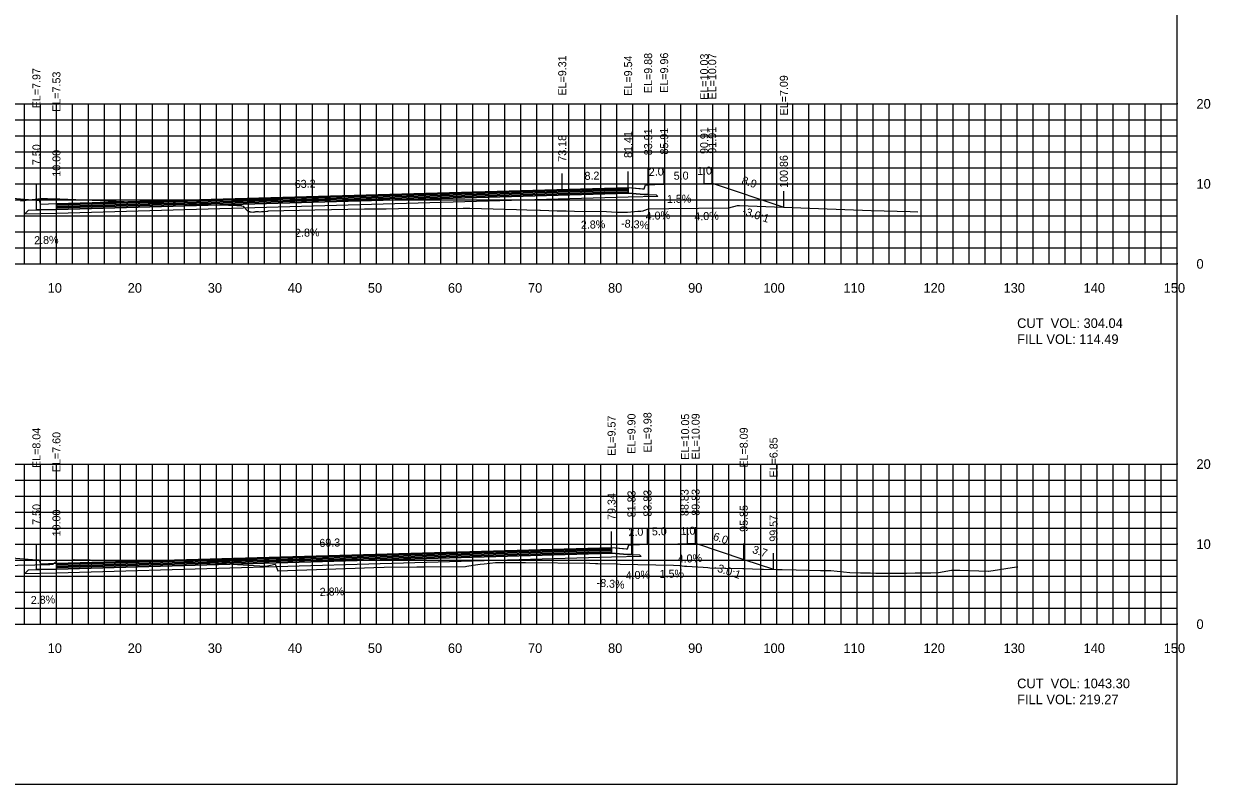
# Model space of a CAD drawing. Extents: x 1797419 to 1809236, y 248759 to 251512.
# Drawn here: x 1806376.9 to 1806525.1, y 250079.4 to 250174.4 of the extents above; entities that cross this region are included whole.
import ezdxf

# ---------------------------------------------------------------- set-up
doc = ezdxf.new("R2010")
doc.units = 0
for name, color, linetype in [('10', 7, 'Continuous'), ('3', 7, 'Continuous'), ('31', 7, 'Continuous'), ('4', 7, 'Continuous'), ('60', 7, 'Continuous'), ('ANNO-TXT', 7, 'Continuous'), ('BASE', 7, 'Continuous'), ('CL-CNST', 7, 'Continuous'), ('Level 62', 7, 'Continuous'), ('LOWER BINDER', 7, 'Continuous'), ('M-ROADS', 7, 'Continuous'), ('UPPER BINDER', 7, 'Continuous'), ('WEARING', 7, 'Continuous')]:
    doc.layers.add(name, color=color, linetype=linetype)

msp = doc.modelspace()

# ---------------------------------------------------------------- linework, layer by layer
for p, q in [((1806461.91, 250154.46), (1806461.91, 250156.46)), ((1806462.91, 250154.5), (1806462.91, 250156.5)), ((1806444.18, 250153.74), (1806444.18, 250155.74)), ((1806452.41, 250153.97), (1806452.41, 250155.97)), ((1806454.91, 250154.31), (1806454.91, 250156.31)), ((1806456.91, 250154.39), (1806456.91, 250156.39)), ((1806378.5, 250152.41), (1806378.5, 250154.41)), ((1806381, 250151.96), (1806381, 250153.96)), ((1806381, 250151.96), (1806381, 250153.96)), ((1806471.86, 250151.52), (1806471.86, 250153.52)), ((1806450.34, 250109), (1806450.34, 250111)), ((1806452.83, 250109.33), (1806452.83, 250111.33)), ((1806454.83, 250109.41), (1806454.83, 250111.41)), ((1806459.83, 250109.49), (1806459.83, 250111.49)), ((1806460.84, 250109.53), (1806460.84, 250111.53)), ((1806378.5, 250107.48), (1806378.5, 250109.48)), ((1806381, 250107.03), (1806381, 250109.03)), ((1806381, 250107.03), (1806381, 250109.03)), ((1806466.85, 250107.52), (1806466.85, 250109.52)), ((1806470.57, 250106.28), (1806470.57, 250108.28))]:
    msp.add_line(p, q)
for points in [[(1806221, 250079.43), (1806521, 250079.43), (1806521, 250269.43), (1806221, 250269.43)], [(1806452.41, 250153.97), (1806454.41, 250153.81), (1806454.58, 250154.31), (1806454.91, 250154.31), (1806454.91, 250153.09), (1806454.41, 250153.09), (1806452.41, 250153.25)], [(1806378.5, 250152.41), (1806378.83, 250152.41), (1806379, 250151.91), (1806381, 250151.96), (1806381, 250151.24), (1806379, 250151.19), (1806378.5, 250151.19)], [(1806450.34, 250109), (1806452.34, 250108.83), (1806452.5, 250109.33), (1806452.83, 250109.33), (1806452.83, 250108.12), (1806452.34, 250108.12), (1806450.34, 250108.28)], [(1806378.5, 250107.48), (1806378.83, 250107.48), (1806379, 250106.98), (1806381, 250107.03), (1806381, 250106.31), (1806379, 250106.26), (1806378.5, 250106.26)]]:
    msp.add_lwpolyline(points, close=True)
at = {"layer": '60'}
for p, q in [((1806521, 250144.43), (1806521, 250164.43)), ((1806521.06, 250164.43), (1806521, 250164.43)), ((1806521.06, 250154.43), (1806521, 250154.43)), ((1806221, 250144.43), (1806521, 250144.43)), ((1806381, 250144.37), (1806381, 250144.43)), ((1806391, 250144.37), (1806391, 250144.43)), ((1806401, 250144.37), (1806401, 250144.43)), ((1806411, 250144.37), (1806411, 250144.43)), ((1806421, 250144.37), (1806421, 250144.43)), ((1806431, 250144.37), (1806431, 250144.43)), ((1806441, 250144.37), (1806441, 250144.43)), ((1806451, 250144.37), (1806451, 250144.43)), ((1806461, 250144.37), (1806461, 250144.43)), ((1806471, 250144.37), (1806471, 250144.43)), ((1806481, 250144.37), (1806481, 250144.43)), ((1806491, 250144.37), (1806491, 250144.43)), ((1806501, 250144.37), (1806501, 250144.43)), ((1806511, 250144.37), (1806511, 250144.43)), ((1806521, 250144.37), (1806521, 250144.43)), ((1806521.06, 250144.43), (1806521, 250144.43)), ((1806521, 250099.43), (1806521, 250119.43)), ((1806521.06, 250119.43), (1806521, 250119.43)), ((1806521.06, 250109.43), (1806521, 250109.43)), ((1806221, 250099.43), (1806521, 250099.43)), ((1806381, 250099.37), (1806381, 250099.43)), ((1806391, 250099.37), (1806391, 250099.43)), ((1806401, 250099.37), (1806401, 250099.43)), ((1806411, 250099.37), (1806411, 250099.43)), ((1806421, 250099.37), (1806421, 250099.43)), ((1806431, 250099.37), (1806431, 250099.43)), ((1806441, 250099.37), (1806441, 250099.43)), ((1806451, 250099.37), (1806451, 250099.43)), ((1806461, 250099.37), (1806461, 250099.43)), ((1806471, 250099.37), (1806471, 250099.43)), ((1806481, 250099.37), (1806481, 250099.43)), ((1806491, 250099.37), (1806491, 250099.43)), ((1806501, 250099.37), (1806501, 250099.43)), ((1806511, 250099.37), (1806511, 250099.43)), ((1806521, 250099.37), (1806521, 250099.43)), ((1806521.06, 250099.43), (1806521, 250099.43))]:
    msp.add_line(p, q, dxfattribs=at)
at = {"layer": 'BASE'}
for points in [[(1806381, 250151.24), (1806452.41, 250153.25), (1806454.41, 250153.09), (1806454.91, 250153.09), (1806455.91, 250153.07), (1806456.12, 250152.86), (1806452.41, 250152.75), (1806381, 250150.74), (1806377, 250150.63), (1806377.5, 250151.13), (1806378.5, 250151.19), (1806379, 250151.19)], [(1806381, 250106.31), (1806450.34, 250108.28), (1806452.34, 250108.12), (1806452.83, 250108.12), (1806453.83, 250108.1), (1806454.05, 250107.88), (1806450.34, 250107.78), (1806381, 250105.81), (1806377, 250105.7), (1806377.5, 250106.2), (1806378.5, 250106.26), (1806379, 250106.26)]]:
    msp.add_lwpolyline(points, close=True, dxfattribs=at)
at = {"layer": 'CL-CNST'}
for points in [[(1806371, 250153.02), (1806378.5, 250152.41), (1806378.58, 250152.41), (1806378.83, 250152.41), (1806378.98, 250151.96), (1806379, 250151.91), (1806381, 250151.96), (1806381, 250151.96), (1806444.18, 250153.74), (1806452.41, 250153.97), (1806454.21, 250153.82), (1806454.41, 250153.81), (1806454.58, 250154.31), (1806454.78, 250154.31), (1806454.91, 250154.31), (1806455.76, 250154.34), (1806456.91, 250154.39), (1806458.9, 250154.42), (1806461.91, 250154.46), (1806462.91, 250154.5), (1806471.86, 250151.52)], [(1806373.81, 250107.86), (1806378.5, 250107.48), (1806378.83, 250107.48), (1806379, 250106.98), (1806380.17, 250107.01), (1806381, 250107.03), (1806381, 250107.03), (1806450.34, 250109), (1806452.18, 250108.84), (1806452.34, 250108.83), (1806452.34, 250108.85), (1806452.5, 250109.33), (1806452.67, 250109.33), (1806452.83, 250109.33), (1806454.83, 250109.41), (1806458.6, 250109.47), (1806459.83, 250109.49), (1806460.84, 250109.53), (1806466.85, 250107.52), (1806470.57, 250106.28)]]:
    msp.add_lwpolyline(points, dxfattribs=at)
at = {"layer": 'Level 62'}
for p, q in [((1806221, 250164.43), (1806521, 250164.43)), ((1806377, 250144.43), (1806377, 250164.43)), ((1806379, 250144.43), (1806379, 250164.43)), ((1806381, 250144.43), (1806381, 250164.43)), ((1806383, 250144.43), (1806383, 250164.43)), ((1806385, 250144.43), (1806385, 250164.43)), ((1806387, 250144.43), (1806387, 250164.43)), ((1806389, 250144.43), (1806389, 250164.43)), ((1806391, 250144.43), (1806391, 250164.43)), ((1806393, 250144.43), (1806393, 250164.43)), ((1806395, 250144.43), (1806395, 250164.43)), ((1806397, 250144.43), (1806397, 250164.43)), ((1806399, 250144.43), (1806399, 250164.43)), ((1806401, 250144.43), (1806401, 250164.43)), ((1806403, 250144.43), (1806403, 250164.43)), ((1806405, 250144.43), (1806405, 250164.43)), ((1806407, 250144.43), (1806407, 250164.43)), ((1806409, 250144.43), (1806409, 250164.43)), ((1806411, 250144.43), (1806411, 250164.43)), ((1806413, 250144.43), (1806413, 250164.43)), ((1806415, 250144.43), (1806415, 250164.43)), ((1806417, 250144.43), (1806417, 250164.43)), ((1806419, 250144.43), (1806419, 250164.43)), ((1806421, 250144.43), (1806421, 250164.43)), ((1806423, 250144.43), (1806423, 250164.43)), ((1806425, 250144.43), (1806425, 250164.43)), ((1806427, 250144.43), (1806427, 250164.43)), ((1806429, 250144.43), (1806429, 250164.43)), ((1806431, 250144.43), (1806431, 250164.43)), ((1806433, 250144.43), (1806433, 250164.43)), ((1806435, 250144.43), (1806435, 250164.43)), ((1806437, 250144.43), (1806437, 250164.43)), ((1806439, 250144.43), (1806439, 250164.43)), ((1806441, 250144.43), (1806441, 250164.43)), ((1806443, 250144.43), (1806443, 250164.43)), ((1806445, 250144.43), (1806445, 250164.43)), ((1806447, 250144.43), (1806447, 250164.43)), ((1806449, 250144.43), (1806449, 250164.43)), ((1806451, 250144.43), (1806451, 250164.43)), ((1806453, 250144.43), (1806453, 250164.43)), ((1806455, 250144.43), (1806455, 250164.43)), ((1806457, 250144.43), (1806457, 250164.43)), ((1806459, 250144.43), (1806459, 250164.43)), ((1806461, 250144.43), (1806461, 250164.43)), ((1806463, 250144.43), (1806463, 250164.43)), ((1806465, 250144.43), (1806465, 250164.43)), ((1806467, 250144.43), (1806467, 250164.43)), ((1806469, 250144.43), (1806469, 250164.43)), ((1806471, 250144.43), (1806471, 250164.43)), ((1806473, 250144.43), (1806473, 250164.43)), ((1806475, 250144.43), (1806475, 250164.43)), ((1806477, 250144.43), (1806477, 250164.43)), ((1806479, 250144.43), (1806479, 250164.43)), ((1806481, 250144.43), (1806481, 250164.43)), ((1806483, 250144.43), (1806483, 250164.43)), ((1806485, 250144.43), (1806485, 250164.43)), ((1806487, 250144.43), (1806487, 250164.43)), ((1806489, 250144.43), (1806489, 250164.43)), ((1806491, 250144.43), (1806491, 250164.43)), ((1806493, 250144.43), (1806493, 250164.43)), ((1806495, 250144.43), (1806495, 250164.43)), ((1806497, 250144.43), (1806497, 250164.43)), ((1806499, 250144.43), (1806499, 250164.43)), ((1806501, 250144.43), (1806501, 250164.43)), ((1806503, 250144.43), (1806503, 250164.43)), ((1806505, 250144.43), (1806505, 250164.43)), ((1806507, 250144.43), (1806507, 250164.43)), ((1806509, 250144.43), (1806509, 250164.43)), ((1806511, 250144.43), (1806511, 250164.43)), ((1806513, 250144.43), (1806513, 250164.43)), ((1806515, 250144.43), (1806515, 250164.43)), ((1806517, 250144.43), (1806517, 250164.43)), ((1806519, 250144.43), (1806519, 250164.43)), ((1806521, 250144.43), (1806521, 250164.43)), ((1806221, 250162.43), (1806521, 250162.43)), ((1806221, 250160.43), (1806521, 250160.43)), ((1806221, 250158.43), (1806521, 250158.43)), ((1806221, 250156.43), (1806521, 250156.43)), ((1806221, 250154.43), (1806521, 250154.43)), ((1806221, 250152.43), (1806521, 250152.43)), ((1806221, 250150.43), (1806521, 250150.43)), ((1806221, 250148.43), (1806521, 250148.43)), ((1806221, 250146.43), (1806521, 250146.43)), ((1806221, 250144.43), (1806521, 250144.43)), ((1806221, 250119.43), (1806521, 250119.43)), ((1806377, 250099.43), (1806377, 250119.43)), ((1806379, 250099.43), (1806379, 250119.43)), ((1806381, 250099.43), (1806381, 250119.43)), ((1806383, 250099.43), (1806383, 250119.43)), ((1806385, 250099.43), (1806385, 250119.43)), ((1806387, 250099.43), (1806387, 250119.43)), ((1806389, 250099.43), (1806389, 250119.43)), ((1806391, 250099.43), (1806391, 250119.43)), ((1806393, 250099.43), (1806393, 250119.43)), ((1806395, 250099.43), (1806395, 250119.43)), ((1806397, 250099.43), (1806397, 250119.43)), ((1806399, 250099.43), (1806399, 250119.43)), ((1806401, 250099.43), (1806401, 250119.43)), ((1806403, 250099.43), (1806403, 250119.43)), ((1806405, 250099.43), (1806405, 250119.43)), ((1806407, 250099.43), (1806407, 250119.43)), ((1806409, 250099.43), (1806409, 250119.43)), ((1806411, 250099.43), (1806411, 250119.43)), ((1806413, 250099.43), (1806413, 250119.43)), ((1806415, 250099.43), (1806415, 250119.43)), ((1806417, 250099.43), (1806417, 250119.43)), ((1806419, 250099.43), (1806419, 250119.43)), ((1806421, 250099.43), (1806421, 250119.43)), ((1806423, 250099.43), (1806423, 250119.43)), ((1806425, 250099.43), (1806425, 250119.43)), ((1806427, 250099.43), (1806427, 250119.43)), ((1806429, 250099.43), (1806429, 250119.43)), ((1806431, 250099.43), (1806431, 250119.43)), ((1806433, 250099.43), (1806433, 250119.43)), ((1806435, 250099.43), (1806435, 250119.43)), ((1806437, 250099.43), (1806437, 250119.43)), ((1806439, 250099.43), (1806439, 250119.43)), ((1806441, 250099.43), (1806441, 250119.43)), ((1806443, 250099.43), (1806443, 250119.43)), ((1806445, 250099.43), (1806445, 250119.43)), ((1806447, 250099.43), (1806447, 250119.43)), ((1806449, 250099.43), (1806449, 250119.43)), ((1806451, 250099.43), (1806451, 250119.43)), ((1806453, 250099.43), (1806453, 250119.43)), ((1806455, 250099.43), (1806455, 250119.43)), ((1806457, 250099.43), (1806457, 250119.43)), ((1806459, 250099.43), (1806459, 250119.43)), ((1806461, 250099.43), (1806461, 250119.43)), ((1806463, 250099.43), (1806463, 250119.43)), ((1806465, 250099.43), (1806465, 250119.43)), ((1806467, 250099.43), (1806467, 250119.43)), ((1806469, 250099.43), (1806469, 250119.43)), ((1806471, 250099.43), (1806471, 250119.43)), ((1806473, 250099.43), (1806473, 250119.43)), ((1806475, 250099.43), (1806475, 250119.43)), ((1806477, 250099.43), (1806477, 250119.43)), ((1806479, 250099.43), (1806479, 250119.43)), ((1806481, 250099.43), (1806481, 250119.43)), ((1806483, 250099.43), (1806483, 250119.43)), ((1806485, 250099.43), (1806485, 250119.43)), ((1806487, 250099.43), (1806487, 250119.43)), ((1806489, 250099.43), (1806489, 250119.43)), ((1806491, 250099.43), (1806491, 250119.43)), ((1806493, 250099.43), (1806493, 250119.43)), ((1806495, 250099.43), (1806495, 250119.43)), ((1806497, 250099.43), (1806497, 250119.43)), ((1806499, 250099.43), (1806499, 250119.43)), ((1806501, 250099.43), (1806501, 250119.43)), ((1806503, 250099.43), (1806503, 250119.43)), ((1806505, 250099.43), (1806505, 250119.43)), ((1806507, 250099.43), (1806507, 250119.43)), ((1806509, 250099.43), (1806509, 250119.43)), ((1806511, 250099.43), (1806511, 250119.43)), ((1806513, 250099.43), (1806513, 250119.43)), ((1806515, 250099.43), (1806515, 250119.43)), ((1806517, 250099.43), (1806517, 250119.43)), ((1806519, 250099.43), (1806519, 250119.43)), ((1806521, 250099.43), (1806521, 250119.43)), ((1806221, 250117.43), (1806521, 250117.43)), ((1806221, 250115.43), (1806521, 250115.43)), ((1806221, 250113.43), (1806521, 250113.43)), ((1806221, 250111.43), (1806521, 250111.43)), ((1806221, 250109.43), (1806521, 250109.43)), ((1806221, 250107.43), (1806521, 250107.43)), ((1806221, 250105.43), (1806521, 250105.43)), ((1806221, 250103.43), (1806521, 250103.43)), ((1806221, 250101.43), (1806521, 250101.43)), ((1806221, 250099.43), (1806521, 250099.43))]:
    msp.add_line(p, q, dxfattribs=at)
at = {"layer": 'LOWER BINDER'}
for points in [[(1806381, 250151.62), (1806452.41, 250153.63), (1806452.41, 250153.44), (1806381, 250151.44)], [(1806381, 250151.44), (1806452.41, 250153.44), (1806452.41, 250153.25), (1806381, 250151.24)], [(1806381, 250106.69), (1806450.34, 250108.66), (1806450.34, 250108.47), (1806381, 250106.51)], [(1806381, 250106.51), (1806450.34, 250108.47), (1806450.34, 250108.28), (1806381, 250106.31)]]:
    msp.add_lwpolyline(points, close=True, dxfattribs=at)
at = {"layer": 'M-ROADS'}
for points in [[(1806376.5, 250152.32), (1806379.04, 250152.6), (1806379.46, 250152.6), (1806379.86, 250152.6), (1806379.88, 250152.6), (1806381.44, 250152.54), (1806397.48, 250151.9), (1806401.05, 250151.81), (1806401.22, 250151.82), (1806401.46, 250151.81), (1806403.53, 250151.71), (1806403.71, 250151.71), (1806404.01, 250151.71), (1806404.06, 250151.71), (1806404.12, 250151.67), (1806404.38, 250151.63), (1806404.38, 250151.59), (1806404.82, 250151.1), (1806404.85, 250151.1), (1806404.97, 250150.97), (1806404.98, 250150.97), (1806405.01, 250150.97), (1806405.04, 250150.96), (1806405.07, 250150.96), (1806405.1, 250150.96), (1806405.14, 250150.95), (1806405.18, 250150.95), (1806405.22, 250150.95), (1806405.26, 250150.94), (1806405.31, 250150.94), (1806405.67, 250150.91), (1806405.69, 250150.92), (1806405.75, 250150.95), (1806405.75, 250150.95), (1806405.81, 250150.95), (1806405.89, 250150.96), (1806405.98, 250150.96), (1806406.08, 250150.96), (1806406.11, 250150.97), (1806406.22, 250150.96), (1806406.39, 250150.95), (1806406.45, 250150.94), (1806406.62, 250150.96), (1806406.82, 250150.97), (1806406.93, 250150.98), (1806407.27, 250151.02), (1806407.39, 250151.03), (1806407.47, 250151.05), (1806413.26, 250151.18), (1806419.5, 250151.31), (1806422.19, 250151.33), (1806423.71, 250151.34), (1806431.8, 250151.38), (1806431.95, 250151.38), (1806432.63, 250151.38), (1806438.45, 250151.22), (1806439.74, 250151.18), (1806441.39, 250151.15), (1806441.48, 250151.15), (1806443.53, 250151.08), (1806444.69, 250151.06), (1806445.7, 250151.03), (1806449.72, 250150.98), (1806450.34, 250150.94), (1806451.09, 250150.9), (1806451.7, 250150.9), (1806451.85, 250150.9), (1806451.87, 250150.9), (1806452.33, 250150.88), (1806453.63, 250151), (1806453.68, 250151), (1806453.94, 250151.02), (1806453.99, 250151.03), (1806454.28, 250151.07), (1806454.39, 250151.1), (1806454.96, 250151.32), (1806457.49, 250151.37), (1806464.89, 250151.43), (1806464.94, 250151.43), (1806464.95, 250151.43), (1806464.96, 250151.43), (1806465, 250151.45), (1806466.06, 250151.72), (1806466.2, 250151.72), (1806466.25, 250151.72), (1806466.28, 250151.72), (1806466.3, 250151.72), (1806466.31, 250151.72), (1806466.32, 250151.72), (1806466.33, 250151.72), (1806466.33, 250151.72), (1806482.77, 250151.12), (1806487.64, 250150.98), (1806488.58, 250150.94)], [(1806369.63, 250106.68), (1806378.29, 250106.85), (1806379.66, 250106.88), (1806380.14, 250106.88), (1806380.16, 250106.89), (1806380.43, 250106.92), (1806380.43, 250106.92), (1806380.52, 250106.93), (1806380.55, 250106.93), (1806380.56, 250106.93), (1806380.57, 250106.93), (1806380.59, 250106.93), (1806380.59, 250106.93), (1806380.6, 250106.93), (1806381.06, 250107.34), (1806381.15, 250107.43), (1806383.1, 250107.48), (1806383.21, 250107.49), (1806387.25, 250107.41), (1806392.73, 250107.39), (1806397.33, 250107.28), (1806398.1, 250107.22), (1806406.41, 250106.72), (1806407.12, 250106.68), (1806407.16, 250106.68), (1806408.32, 250106.94), (1806408.34, 250106.92), (1806408.37, 250106.84), (1806408.65, 250106.09), (1806418.3, 250106.43), (1806420.66, 250106.51), (1806421.92, 250106.53), (1806426.02, 250106.58), (1806426.93, 250106.59), (1806432.09, 250106.65), (1806432.26, 250106.68), (1806433.06, 250106.79), (1806433.94, 250106.91), (1806434.41, 250106.97), (1806435.85, 250107.15), (1806438.13, 250107.15), (1806439.6, 250107.13), (1806447.62, 250107.03), (1806448.32, 250107.01), (1806448.61, 250107.01), (1806451.1, 250106.95), (1806451.4, 250106.94), (1806458.06, 250106.8), (1806458.88, 250106.74), (1806459.15, 250106.72), (1806459.47, 250106.69), (1806459.76, 250106.67), (1806461.8, 250106.53), (1806462.37, 250106.49), (1806462.61, 250106.48), (1806464.5, 250106.43), (1806464.52, 250106.43), (1806464.58, 250106.43), (1806464.61, 250106.43), (1806466.73, 250106.38), (1806466.83, 250106.37), (1806466.96, 250106.37), (1806468.95, 250106.32), (1806469.32, 250106.31), (1806470.92, 250106.27), (1806470.98, 250106.27), (1806471.25, 250106.27), (1806471.67, 250106.24), (1806473.41, 250106.2), (1806474.99, 250106.17), (1806476.42, 250106.14), (1806477.73, 250106.12), (1806480.09, 250105.9), (1806481.43, 250105.86), (1806482.68, 250105.85), (1806483.37, 250105.81), (1806484.56, 250105.82), (1806486.06, 250105.82), (1806487.19, 250105.82), (1806488.26, 250105.83), (1806489.27, 250105.83), (1806490.23, 250105.84), (1806491.16, 250105.87), (1806492.8, 250106.17), (1806493.84, 250106.16), (1806497.43, 250106.07), (1806497.48, 250106.07), (1806500.9, 250106.6), (1806501.07, 250106.59)]]:
    msp.add_lwpolyline(points, dxfattribs=at)
at = {"layer": 'UPPER BINDER'}
for points in [[(1806381, 250151.81), (1806452.41, 250153.82), (1806452.41, 250153.63), (1806381, 250151.62)], [(1806381, 250106.88), (1806450.34, 250108.85), (1806450.34, 250108.66), (1806381, 250106.69)]]:
    msp.add_lwpolyline(points, close=True, dxfattribs=at)
at = {"layer": 'WEARING'}
for points in [[(1806381, 250151.96), (1806452.41, 250153.97), (1806452.41, 250153.82), (1806381, 250151.81)], [(1806381, 250107.03), (1806450.34, 250109), (1806450.34, 250108.85), (1806381, 250106.88)]]:
    msp.add_lwpolyline(points, close=True, dxfattribs=at)

# ---------------------------------------------------------------- texts
for rotation, p in [(341.5639, (1806466.59, 250150.64)), (341.5676, (1806463.05, 250106.15))]:
    msp.add_text('-3.0:1', height=1, rotation=rotation).set_placement(p)
at = {"layer": '10'}
for s, p in [('10', (1806379.9, 250140.83)), ('20', (1806389.9, 250140.83)), ('30', (1806399.9, 250140.83)), ('40', (1806409.9, 250140.83)), ('50', (1806419.9, 250140.83)), ('60', (1806429.9, 250140.83)), ('70', (1806439.9, 250140.83)), ('80', (1806449.9, 250140.83)), ('90', (1806459.9, 250140.83)), ('100', (1806469.3, 250140.83)), ('110', (1806479.3, 250140.83)), ('120', (1806489.3, 250140.83)), ('130', (1806499.3, 250140.83)), ('140', (1806509.3, 250140.83)), ('150', (1806519.3, 250140.83)), ('10', (1806379.9, 250095.83)), ('20', (1806389.9, 250095.83)), ('30', (1806399.9, 250095.83)), ('40', (1806409.9, 250095.83)), ('50', (1806419.9, 250095.83)), ('60', (1806429.9, 250095.83)), ('70', (1806439.9, 250095.83)), ('80', (1806449.9, 250095.83)), ('90', (1806459.9, 250095.83)), ('100', (1806469.3, 250095.83)), ('110', (1806479.3, 250095.83)), ('120', (1806489.3, 250095.83)), ('130', (1806499.3, 250095.83)), ('140', (1806509.3, 250095.83)), ('150', (1806519.3, 250095.83))]:
    msp.add_text(s, height=1.2, dxfattribs=at).set_placement(p)
at = {"layer": '3'}
for s, p in [('EL=9.31', (1806444.68, 250165.46)), ('EL=9.54', (1806452.91, 250165.44)), ('EL=9.88', (1806455.41, 250165.77)), ('EL=9.96', (1806457.41, 250165.8)), ('EL=10.03', (1806462.41, 250164.93)), ('EL=10.07', (1806463.41, 250164.97)), ('EL=7.97', (1806379, 250163.87)), ('EL=7.53', (1806381.5, 250163.43)), ('EL=7.53', (1806381.5, 250163.43)), ('EL=7.09', (1806472.36, 250162.98)), ('81.41', (1806452.91, 250157.67)), ('83.91', (1806455.41, 250158.01)), ('85.91', (1806457.41, 250158.09)), ('90.91', (1806462.41, 250158.16)), ('91.91', (1806463.41, 250158.2)), ('73.18', (1806444.68, 250157.19)), ('7.50', (1806379, 250156.77)), ('10.00', (1806381.5, 250155.33)), ('10.00', (1806381.5, 250155.33)), ('100.86', (1806472.36, 250153.93)), ('EL=9.57', (1806450.84, 250120.46)), ('EL=9.90', (1806453.33, 250120.72)), ('EL=9.98', (1806455.33, 250120.88)), ('EL=10.05', (1806460.03, 250119.96)), ('EL=10.09', (1806461.34, 250120)), ('EL=8.04', (1806379, 250118.94)), ('EL=8.09', (1806467.35, 250118.99)), ('EL=7.60', (1806381.5, 250118.42)), ('EL=7.60', (1806381.5, 250118.42)), ('EL=6.85', (1806471.07, 250117.75)), ('79.34', (1806450.84, 250112.45)), ('81.83', (1806453.33, 250112.78)), ('83.83', (1806455.33, 250112.86)), ('88.83', (1806459.96, 250112.94)), ('89.83', (1806461.34, 250112.98)), ('7.50', (1806379, 250111.84)), ('10.00', (1806381.5, 250110.4)), ('10.00', (1806381.5, 250110.4)), ('95.85', (1806467.35, 250110.97)), ('99.57', (1806471.07, 250109.73))]:
    msp.add_text(s, height=1, rotation=90, dxfattribs=at).set_placement(p)
at = {"layer": '31'}
for s, p in [('20', (1806523.4, 250163.83)), ('10', (1806523.4, 250153.83)), ('0', (1806523.4, 250143.83)), ('20', (1806523.4, 250118.83)), ('10', (1806523.4, 250108.83)), ('0', (1806523.4, 250098.83))]:
    msp.add_text(s, height=1.2, dxfattribs=at).set_placement(p)
at = {"layer": '4'}
for s, rotation, p in [('2.0', 2.2901, (1806455.01, 250155.41)), ('1.0', 2.2901, (1806461.04, 250155.53)), ('63.2', 1.6131, (1806410.78, 250153.9)), ('8.2', 1.6131, (1806446.98, 250154.92)), ('5.0', 0.8594, (1806458.11, 250154.94)), ('8.9', 341.5639, (1806466.51, 250154.46)), ('1.5%', 0.8594, (1806457.26, 250152.04)), ('4.0%', 2.2901, (1806454.62, 250149.91)), ('4.0%', 2.2901, (1806460.7, 250149.85)), ('2.8%', 1.6131, (1806446.52, 250148.81)), ('-8.3%', 355.2542, (1806451.5, 250149.03)), ('2.8%', 1.6035, (1806378.23, 250146.88)), ('2.8%', 1.6131, (1806410.82, 250147.8)), ('2.0', 2.2906, (1806452.47, 250110.42)), ('5.0', 0.8594, (1806455.38, 250110.52)), ('1.0', 2.2896, (1806458.97, 250110.55)), ('6.0', 341.5676, (1806462.94, 250109.99)), ('69.3', 1.6242, (1806413.86, 250109.07)), ('3.7', 341.5676, (1806467.84, 250108.35)), ('4.0%', 2.2896, (1806458.62, 250107.08)), ('4.0%', 2.2906, (1806452.12, 250105.02)), ('1.5%', 0.8594, (1806456.35, 250105.21)), ('-8.3%', 355.2269, (1806448.44, 250104.14)), ('2.8%', 1.6242, (1806413.9, 250102.96)), ('2.8%', 1.6042, (1806377.81, 250101.94))]:
    msp.add_text(s, height=1, rotation=rotation, dxfattribs=at).set_placement(p)
at = {"layer": 'ANNO-TXT'}
for s, p in [('CUT  VOL: 304.04', (1806501, 250136.43)), ('FILL VOL: 114.49', (1806501, 250134.43)), ('CUT  VOL: 1043.30', (1806501, 250091.43)), ('FILL VOL: 219.27', (1806501, 250089.43))]:
    msp.add_text(s, height=1.2, dxfattribs=at).set_placement(p)

doc.saveas('drawing.dxf')
